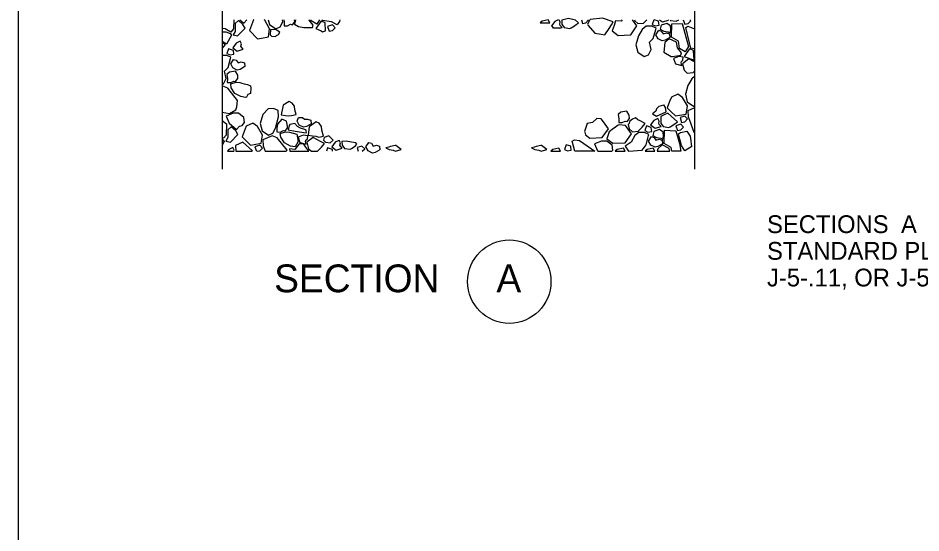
# Model space of a CAD drawing. Extents: x 99862 to 103151, y 100000 to 108153.
# Drawn here: x 99862 to 100674, y 101054 to 101517 of the extents above; entities that cross this region are included whole.
import ezdxf

# ---------------------------------------------------------------- set-up
doc = ezdxf.new("R2010")
doc.units = 0
for name, color, linetype in [('Level 1', 7, 'Continuous'), ('Level 14', 7, 'Continuous'), ('Level 15', 7, 'Continuous'), ('Level 20', 7, 'Continuous'), ('Level 9', 7, 'Continuous')]:
    doc.layers.add(name, color=color, linetype=linetype)

msp = doc.modelspace()

# ---------------------------------------------------------------- linework, layer by layer
at = {"layer": 'Level 1'}
msp.add_lwpolyline([(99862, 99999.5), (103151, 99999.5), (103151, 102075.5), (99862, 102075.5)], close=True, dxfattribs=at)
at = {"layer": 'Level 14'}
for points in [[(100351.01, 101515.54), (100357.28, 101517.09), (100363.3, 101515.48)], [(100349.83, 101508.22), (100343.6, 101508.22), (100342.81, 101509.46)]]:
    msp.add_lwpolyline(points, dxfattribs=at)
at = {"layer": 'Level 15'}
for points in [[(100470.57, 101887.78), (100470.57, 101714.5), (100486.06, 101714.5), (100455.09, 101683.53), (100470.57, 101683.53), (100470.57, 101381.32)], [(100045.57, 101549.08), (100045.57, 101381.32)]]:
    msp.add_lwpolyline(points, dxfattribs=at)
at = {"layer": 'Level 20'}
for p, q in [((100135.92, 101504.91), (100138.62, 101505.77)), ((100106.32, 101397.32), (100123.59, 101397.32)), ((100380.81, 101397.32), (100362.75, 101397.32)), ((100458.16, 101397.32), (100450.04, 101397.32))]:
    msp.add_line(p, q, dxfattribs=at)
for points in [[(100056.06, 101515.66), (100055.65, 101507.47), (100053.3, 101504.62), (100048.44, 101507.37), (100045.57, 101507.74)], [(100061.52, 101515.66), (100065.04, 101512.62), (100067.67, 101515.66)], [(100074.07, 101515.66), (100073.8, 101515.53), (100070.11, 101505.93), (100077.5, 101498.54), (100081.04, 101499.13), (100087.2, 101500.15), (100088.29, 101507.55), (100083.85, 101515.24), (100083.27, 101515.66)], [(100086.99, 101515.66), (100088.09, 101511.29), (100093.86, 101507.45), (100097.77, 101509.15), (100100.14, 101513.88), (100099.74, 101515.66)], [(100101.14, 101515.66), (100101.43, 101513.47), (100101.28, 101510.3), (100104.46, 101510.15), (100107.2, 101511.55), (100108.79, 101511.22), (100110.89, 101513.77), (100110.78, 101515.66)], [(100111.6, 101515.66), (100110.73, 101511.55), (100114.37, 101509.47), (100119.12, 101508.59), (100126.95, 101508.63), (100127.54, 101510.92), (100123.75, 101515.3), (100123.7, 101515.66)], [(100133.14, 101515.66), (100130.63, 101511.7), (100125.75, 101514.8), (100125.61, 101515.66)], [(100138.62, 101505.77), (100138.31, 101513.03), (100134.99, 101514.29), (100134.99, 101514.29), (100134.39, 101514.14), (100129.81, 101507.64), (100134.6, 101505.83), (100135.92, 101504.91)], [(100151.34, 101515.66), (100151.25, 101514.01), (100148.9, 101511.16), (100144.03, 101513.91), (100135.95, 101514.95), (100135.77, 101515.66)], [(100340.31, 101512.84), (100338.8, 101515.58), (100333.4, 101514.48), (100331.59, 101512.84)], [(100331.59, 101512.84), (100340.31, 101512.84)], [(100347.97, 101515.66), (100344.89, 101514.12), (100341.93, 101510.1), (100342.89, 101509.39)], [(100349.48, 101508.22), (100351.38, 101508.8), (100349.71, 101510.5), (100349.31, 101511.6), (100349.73, 101513.54), (100348.68, 101515.66)], [(100351.1, 101515.66), (100351.14, 101511.64), (100353.28, 101508.59), (100358.42, 101507.84), (100359.67, 101508.5), (100362.46, 101510.23), (100362.87, 101510.48), (100366.21, 101512.98), (100363.19, 101515.66)], [(100368.75, 101515.66), (100369.76, 101512.39), (100369.76, 101512.39), (100372.72, 101512.98)], [(100372.72, 101512.98), (100375.23, 101515.49), (100375.07, 101515.66)], [(100376.38, 101515.66), (100374.26, 101511.73), (100374.68, 101510.59), (100380.85, 101503.67), (100386.62, 101502.68), (100389.94, 101502.12), (100393.64, 101507.88), (100395.7, 101511.11), (100397.33, 101513.65), (100387.57, 101516.97), (100376.64, 101515.85)], [(100405.47, 101515.66), (100404.43, 101514.24), (100399.55, 101514.83), (100398.1, 101510.56), (100396.44, 101505.66), (100401.84, 101501.6), (100407.23, 101501.85), (100413.15, 101502.12), (100418.61, 101510.11), (100414.76, 101515.66)], [(100416.45, 101515.66), (100416.67, 101514.76), (100419.44, 101512.29), (100424.61, 101512.73), (100425.68, 101513.66), (100427.68, 101515.66)], [(100433.78, 101515.66), (100432.32, 101511.52), (100432.32, 101511.52), (100435.05, 101510.23)], [(100435.05, 101510.23), (100438.56, 101510.75), (100438.05, 101514.27), (100434.09, 101515.66)], [(100438.86, 101515.66), (100441.55, 101513.68), (100446.98, 101515.34), (100446.67, 101515.66)], [(100448.51, 101515.66), (100448.88, 101515.13), (100454.02, 101514.38), (100455.27, 101515.04), (100456.27, 101515.66)], [(100460.42, 101515.66), (100461.68, 101511.59), (100461.68, 101511.59), (100464.64, 101512.18)], [(100464.64, 101512.18), (100467.15, 101514.69), (100466.19, 101515.66)], [(100045.57, 101504.92), (100048.75, 101504.9), (100052.81, 101503.16), (100054.06, 101501.74), (100049.56, 101493.84), (100045.57, 101496.07)], [(100093.58, 101500.45), (100093.63, 101500.65), (100094.34, 101501.58), (100096.2, 101502.28), (100097.58, 101504.57), (100094.08, 101506.67), (100089.09, 101507), (100088.77, 101502.01), (100089.93, 101501.02)], [(100144.77, 101505.98), (100147.28, 101508.5), (100144.77, 101511.01), (100140.48, 101509.68), (100141.81, 101505.39), (100141.81, 101505.39), (100144.77, 101505.98)], [(100435.87, 101508.15), (100432.1, 101509.77), (100427.03, 101509.81), (100423.49, 101507), (100420.09, 101501.09), (100417.72, 101493.11), (100419.42, 101486.38), (100425.19, 101482.54), (100429.1, 101484.24), (100431.47, 101488.97), (100429.99, 101495.47), (100433.39, 101498.73), (100435.62, 101507.04), (100435.87, 101508.15)], [(100470.57, 101489.62), (100467.28, 101490.04), (100466.05, 101494.88), (100462.55, 101508.69), (100464.53, 101509.88), (100470.57, 101507.55)], [(100089.93, 101501.02), (100093.58, 101500.45)], [(100045.57, 101489.78), (100045.95, 101490.16), (100048.62, 101493.35), (100045.57, 101495)], [(100052.65, 101484.07), (100056.17, 101484.59), (100055.65, 101488.11), (100051.41, 101489.6), (100049.93, 101485.36), (100049.93, 101485.36), (100052.65, 101484.07)], [(100053.47, 101482), (100049.71, 101483.61), (100045.57, 101483.64)], [(100045.57, 101457.59), (100046.7, 101458.08), (100049.07, 101462.81), (100047.59, 101469.31), (100050.99, 101472.57), (100053.22, 101480.88), (100053.47, 101482)], [(100470.57, 101477.67), (100465.35, 101480.49), (100459.76, 101476.11), (100461.2, 101470.23), (100463.97, 101467.76), (100469.14, 101468.2), (100470.21, 101469.13), (100470.57, 101469.48)], [(100470.57, 101464.5), (100468.02, 101462.47), (100464.62, 101456.56), (100462.25, 101448.58), (100463.95, 101441.85), (100469.72, 101438.01), (100470.57, 101438.38)], [(100045.57, 101432.54), (100052.07, 101431.43), (100057.98, 101434.73), (100058.66, 101437.19), (100059.46, 101442.96), (100050.67, 101453.97), (100046.09, 101455.89), (100045.57, 101455.66)], [(100066.53, 101445.83), (100062.39, 101446.51), (100057, 101449.47), (100053.74, 101454.5), (100053.34, 101458.01), (100058.18, 101459.37), (100061.5, 101459.15), (100063.29, 101458.69)], [(100063.29, 101458.69), (100065.27, 101458.1), (100068.38, 101457.41), (100071.13, 101456.16), (100071.49, 101454.03), (100071.04, 101449.41), (100068.81, 101448.48), (100068.07, 101447.3), (100067.51, 101446.15), (100066.53, 101445.83)], [(100108.61, 101440.73), (100106, 101442.2), (100100.62, 101438.88), (100098.77, 101430.23), (100102.53, 101429.43)], [(100102.53, 101429.43), (100105.63, 101429.21), (100107.89, 101429.52), (100112.18, 101430.39), (100111, 101434.53), (100110.81, 101437.78), (100108.61, 101440.73)], [(100086.98, 101435.45), (100082.22, 101430.4), (100079.85, 101422.42), (100081.55, 101415.69), (100087.32, 101411.85), (100091.23, 101413.55), (100093.6, 101418.28), (100096.17, 101428.45), (100096.06, 101434.14), (100091.75, 101435.7), (100086.86, 101435.41)], [(100436.42, 101435.65), (100435.55, 101433.38), (100432.71, 101431.13), (100436.29, 101428.89), (100444.86, 101432.81), (100444.36, 101436.71), (100443.03, 101439.15)], [(100443.03, 101439.15), (100442.59, 101438.83), (100438.27, 101437.66), (100436.42, 101435.65)], [(100470.57, 101436.44), (100464.51, 101433.75), (100464.81, 101428.28), (100465.92, 101425.3), (100468.74, 101417.74), (100469.91, 101414.61), (100470.57, 101414.5)], [(100045.57, 101425.06), (100049.62, 101422.13), (100049.11, 101411.87), (100046.76, 101409.03), (100045.57, 101409.7)], [(100099.13, 101426.22), (100095.35, 101421.79), (100094.89, 101417.87), (100094.75, 101414.7), (100097.92, 101414.55), (100100.66, 101415.95), (100102.25, 101415.62), (100104.35, 101418.17), (100104.24, 101419.93)], [(100104.24, 101419.93), (100103.44, 101424.3), (100099.13, 101426.22)], [(100132.89, 101422.49), (100130.29, 101423.96), (100123.92, 101419.43), (100123.06, 101411.99), (100126.82, 101411.19)], [(100372.3, 101412.07), (100376.2, 101409.14), (100387.51, 101409.65), (100392.97, 101417.64), (100388.62, 101423.92), (100386.62, 101426.44), (100382.55, 101426.87), (100378.79, 101423.23), (100373.91, 101422.36), (100371.49, 101415.23)], [(100419.59, 101425.77), (100417.38, 101427.57), (100414.78, 101426.33), (100411.98, 101424.21), (100411.6, 101422.4), (100410.86, 101421.4)], [(100410.86, 101421.4), (100411.83, 101417.46), (100414.6, 101414.99), (100419.77, 101415.43), (100420.84, 101416.36), (100423.5, 101419.02), (100426.18, 101422.21), (100421.68, 101424.64), (100419.59, 101425.77)], [(100461.78, 101423.92), (100464.29, 101426.43), (100461.78, 101428.95), (100457.49, 101427.62), (100458.82, 101423.33), (100458.82, 101423.33), (100461.78, 101423.92)], [(100105.81, 101420.42), (100105.02, 101416.74), (100111.4, 101415.37), (100121.25, 101413.82), (100121.55, 101414.99)], [(100121.55, 101414.99), (100120.73, 101416.53), (100116.07, 101418.1), (100113.22, 101419.53), (100110.88, 101422.26), (100106.45, 101421.55), (100105.81, 101420.42)], [(100126.82, 101411.19), (100129.91, 101410.97), (100132.42, 101410.07), (100136.71, 101410.93), (100135.28, 101416.29), (100135.09, 101419.54), (100132.89, 101422.49)], [(100371.49, 101415.23), (100371.77, 101414.48), (100372.3, 101412.07)], [(100393.68, 101414.93), (100391.54, 101408.61), (100396.94, 101404.55), (100408.25, 101405.07), (100413.71, 101413.06), (100409.35, 101419.33), (100408.38, 101420.56)], [(100408.38, 101420.56), (100402.72, 101421.22), (100401.71, 101420.83), (100398.3, 101418.11), (100397.55, 101417.85), (100393.69, 101414.93), (100393.68, 101414.93)], [(100428.51, 101414.63), (100432.03, 101415.15), (100431.51, 101418.67), (100427.27, 101420.15), (100425.78, 101415.92), (100425.78, 101415.92), (100428.51, 101414.63)], [(100450.04, 101397.32), (100449.5, 101400.65), (100443.15, 101404.35), (100443.55, 101416.26), (100453.65, 101415.84), (100456.94, 101404.25), (100458.16, 101397.32)], [(100458.1, 101416.58), (100460.61, 101419.09), (100458.1, 101421.61), (100453.81, 101420.28), (100455.14, 101415.99), (100455.14, 101415.99), (100458.1, 101416.58)], [(100467.94, 101401.78), (100461.86, 101397.7), (100458.66, 101402.61), (100457.22, 101408.29), (100456.01, 101413.09), (100457.99, 101414.28), (100463.66, 101415.3), (100466.59, 101410.96), (100467.17, 101406.81), (100467.61, 101403.71), (100467.88, 101401.71)], [(100045.57, 101407.86), (100046.27, 101407.56), (100047.52, 101406.14), (100045.57, 101402.73)], [(100103.28, 101397.32), (100103.99, 101398.43), (100095.2, 101409.44), (100090.62, 101411.36), (100082.12, 101407.59), (100082.41, 101402.12), (100084.2, 101397.32)], [(100128.98, 101397.32), (100131.27, 101397.51), (100132.35, 101398.44), (100135.01, 101401.1), (100137.68, 101404.29), (100134.11, 101406.22), (100127.49, 101409.8), (100121.89, 101405.42), (100123.33, 101399.55), (100125.82, 101397.32)], [(100142.89, 101404.81), (100145.41, 101407.32), (100141.55, 101411.18), (100137.26, 101409.85), (100136.84, 101407.44), (100138.59, 101405.56), (100142.96, 101404.82)], [(100150.02, 101406.87), (100147.15, 101405.44), (100144.19, 101401.42), (100148.21, 101398.46), (100153.64, 101400.12), (100151.98, 101401.82), (100151.57, 101402.92), (100151.99, 101404.86), (100151.1, 101406.65)], [(100151.1, 101406.65), (100150.59, 101406.75), (100150.02, 101406.87)], [(100362.75, 101397.32), (100360.41, 101406.55), (100362.39, 101407.74), (100367.03, 101406.97), (100370.99, 101404.42), (100380.81, 101397.32)], [(100429.33, 101412.55), (100425.56, 101414.17), (100420.49, 101414.21), (100416.95, 101411.4), (100413.55, 101405.49), (100408.1, 101401.8), (100411.23, 101397.32)], [(100411.12, 101397.33), (100423.45, 101398.41), (100426.85, 101403.13), (100429.08, 101411.44), (100429.33, 101412.55)], [(100056.18, 101397.32), (100056.39, 101398.32), (100055.2, 101400.72), (100051.55, 101398.9), (100050.38, 101397.32)], [(100072.27, 101397.32), (100072.87, 101397.77), (100064.19, 101405.45), (100057.74, 101402.47), (100057.8, 101397.32)], [(100079.38, 101397.76), (100081.89, 101400.28), (100079.38, 101402.79), (100075.1, 101401.46), (100076.38, 101397.32)], [(100123.59, 101397.32), (100120.92, 101401.16), (100118.92, 101403.69), (100114.86, 101404.12), (100111.09, 101399.02), (100106.21, 101399.61), (100106.32, 101397.32)], [(100144.96, 101397.32), (100144.71, 101399.05), (100140.47, 101400.54), (100139.34, 101397.32)], [(100166.65, 101403.71), (100165.93, 101404.97), (100161.79, 101405.68), (100157.28, 101406.41), (100153.37, 101406.22)], [(100153.37, 101406.22), (100153.41, 101402.96), (100155.54, 101399.91), (100160.68, 101399.17), (100161.93, 101399.82), (100165.13, 101401.8), (100166.65, 101403.71)], [(100171.66, 101397.32), (100173.82, 101399.48), (100171.3, 101401.99), (100167.02, 101400.66), (100168.05, 101397.32)], [(100192.81, 101400.53), (100195.7, 101398.92), (100199.47, 101398.41), (100201.42, 101397.56), (100206.66, 101398.88), (100201.76, 101402.63)], [(100201.76, 101402.63), (100201.09, 101402.46), (100197.11, 101401.51), (100195.49, 101401.12), (100192.81, 101400.53)], [(100323.9, 101400.53), (100326.79, 101398.92), (100330.56, 101398.41), (100332.52, 101397.56), (100337.75, 101398.88), (100332.85, 101402.63)], [(100332.85, 101402.63), (100332.18, 101402.46), (100328.2, 101401.51), (100326.58, 101401.12), (100323.9, 101400.53)], [(100350, 101397.32), (100348.48, 101400.06), (100343.08, 101398.95), (100341.28, 101397.32)], [(100356.12, 101397.77), (100359.64, 101398.29), (100359.12, 101401.8), (100354.89, 101403.29), (100353.4, 101399.05), (100353.4, 101399.05), (100356.12, 101397.77)], [(100396.19, 101397.32), (100396.93, 101398.31), (100396.33, 101402.75), (100391.6, 101406.59), (100386.87, 101406.59), (100380.67, 101403.93), (100383.33, 101397.72), (100383.8, 101397.32)], [(100407.98, 101397.32), (100406.46, 101400.06), (100401.06, 101398.95), (100399.25, 101397.32)], [(100434.91, 101397.32), (100433.39, 101400.06), (100428, 101398.95), (100426.19, 101397.32)], [(100448.14, 101397.32), (100447.97, 101398.34), (100447.71, 101399.98), (100441.28, 101403.01), (100437.36, 101399.69), (100436.86, 101397.32)], [(100050.38, 101397.32), (100056.18, 101397.32)], [(100057.8, 101397.32), (100072.27, 101397.32)], [(100077.15, 101397.32), (100079.38, 101397.76)], [(100084.2, 101397.32), (100103.28, 101397.32)], [(100125.82, 101397.32), (100128.98, 101397.32)], [(100341.28, 101397.32), (100350, 101397.32)], [(100383.8, 101397.32), (100396.19, 101397.32)], [(100399.25, 101397.32), (100407.98, 101397.32)], [(100426.19, 101397.32), (100434.91, 101397.32)], [(100436.86, 101397.32), (100445.73, 101397.32), (100448.14, 101397.32)]]:
    msp.add_lwpolyline(points, dxfattribs=at)
for points in [[(100066.15, 101507.96), (100064.31, 101511.43), (100060.26, 101514.89), (100057.28, 101512.25), (100057.24, 101505.19), (100055.38, 101502.09), (100059.52, 101501.26)], [(100446.66, 101504.75), (100448.61, 101503.9), (100449.09, 101506.6), (100448.87, 101510.14), (100445.62, 101512.43), (100440.52, 101510.73), (100439.56, 101507.11), (100442.89, 101505.27)], [(100445.21, 101503.82), (100448.06, 101502.97), (100448.28, 101499.65), (100444.11, 101497.17), (100441.52, 101496.58), (100437.68, 101498.58), (100435.68, 101502.12), (100438.3, 101506.15), (100440.59, 101505.41), (100442.33, 101502.94)], [(100450.09, 101511.86), (100459.26, 101512.15), (100465.06, 101491.67), (100461.95, 101486.79), (100457.08, 101489.89), (100456.04, 101496.25), (100449.69, 101499.94)], [(100062.51, 101491.98), (100062.93, 101493.92), (100061.74, 101496.32), (100058.09, 101494.5), (100055.13, 101490.48), (100059.15, 101487.52), (100064.58, 101489.18), (100062.92, 101490.88)], [(100454.25, 101495.58), (100447.82, 101498.61), (100443.9, 101495.29), (100442.77, 101486.64), (100449.53, 101482.69), (100450.77, 101482.49), (100458.28, 101483.72), (100458.87, 101486.01), (100455.08, 101490.39)], [(100465.72, 101489.23), (100461.14, 101482.72), (100470.16, 101479.32), (100469.64, 101488.12), (100466.31, 101489.38), (100466.31, 101489.38)], [(100062.82, 101477.67), (100065.66, 101476.82), (100065.88, 101473.49), (100061.71, 101471.01), (100059.12, 101470.42), (100055.28, 101472.42), (100053.28, 101475.97), (100055.91, 101479.99), (100058.2, 101479.26), (100059.93, 101476.78)], [(100458.72, 101477.96), (100460.12, 101479.36), (100460.42, 101482.02), (100456.36, 101482.47), (100451.7, 101480.69), (100453.48, 101476.03), (100458.94, 101474.48), (100458.46, 101476.81)], [(100056.13, 101460.48), (100057.72, 101460.15), (100059.82, 101462.7), (100059.64, 101465.69), (100057.53, 101469.5), (100052.14, 101468.39), (100049.85, 101466.32), (100050.36, 101462.4), (100050.22, 101459.23), (100053.39, 101459.08)], [(100464.14, 101438.11), (100459.71, 101445.8), (100455.57, 101448.75), (100449.66, 101446.09), (100448.09, 101442.02), (100445.96, 101436.49), (100449.55, 101432.9), (100453.35, 101429.09), (100456.9, 101429.69), (100463.06, 101430.71)], [(100065.6, 101423.23), (100065.01, 101427.66), (100060.28, 101431.5), (100055.55, 101431.5), (100049.34, 101428.84), (100052, 101422.63), (100058.5, 101417.02), (100061.15, 101420.08), (100063.53, 101420.42)], [(100408.22, 101424.51), (100409.81, 101424.18), (100411.91, 101426.73), (100411.73, 101429.72), (100409.62, 101433.53), (100404.23, 101432.42), (100401.94, 101430.35), (100402.45, 101426.43), (100402.31, 101423.25), (100405.48, 101423.1)], [(100448.73, 101419.44), (100451.93, 101421.42), (100455.27, 101423.93), (100449.46, 101429.07), (100446.59, 101431.61), (100443.89, 101430.36), (100440.14, 101428.62), (100440.2, 101422.58), (100442.34, 101419.53), (100447.48, 101418.78)], [(100122.49, 101426.21), (100125.34, 101425.36), (100125.56, 101422.03), (100121.38, 101419.55), (100118.79, 101418.96), (100114.95, 101420.96), (100112.96, 101424.51), (100114.3, 101427.64), (100117.87, 101427.8), (100119.61, 101426.27)], [(100438.37, 101422.54), (100438.79, 101424.48), (100437.6, 101426.88), (100433.95, 101425.06), (100430.99, 101421.04), (100435.01, 101418.08), (100440.44, 101419.74), (100438.77, 101421.44)], [(100059.61, 101412.36), (100057.77, 101415.83), (100053.72, 101419.29), (100050.74, 101416.65), (100050.7, 101409.6), (100048.84, 101406.49), (100052.98, 101405.66)], [(100081.75, 101411.95), (100077.31, 101419.64), (100073.17, 101422.6), (100067.26, 101419.93), (100063.57, 101410.33), (100070.96, 101402.94), (100074.5, 101403.53), (100080.66, 101404.55)], [(100440.12, 101409.15), (100442.07, 101408.3), (100442.55, 101411), (100442.33, 101414.54), (100439.08, 101416.84), (100433.98, 101415.14), (100433.02, 101411.51), (100436.35, 101409.67)], [(100106.03, 101414.62), (100112.83, 101412.85), (100113.35, 101409.45), (100113.87, 101406.05), (100111.36, 101401.25), (100106.92, 101401.98), (100101.53, 101404.94), (100098.27, 101409.97), (100097.87, 101413.48), (100102.71, 101414.84)], [(100120.85, 101407.27), (100122.26, 101408.67), (100122.55, 101411.33), (100118.5, 101411.78), (100113.83, 101410), (100115.61, 101405.34), (100121.07, 101403.8), (100120.59, 101406.12)], [(100438.67, 101408.23), (100441.52, 101407.38), (100441.74, 101404.05), (100437.57, 101401.57), (100434.98, 101400.98), (100431.14, 101402.98), (100429.14, 101406.53), (100431.76, 101410.55), (100434.06, 101409.81), (100435.79, 101407.34)], [(100184.41, 101402.94), (100187.26, 101402.09), (100187.48, 101398.77), (100183.3, 101396.29), (100180.72, 101395.7), (100176.87, 101397.7), (100174.88, 101401.24), (100177.5, 101405.27), (100179.79, 101404.53), (100181.53, 101402.06)]]:
    msp.add_lwpolyline(points, close=True, dxfattribs=at)
at = {"layer": 'Level 9'}
msp.add_circle((100303.86, 101280.07), 37.5, dxfattribs=at)

# ---------------------------------------------------------------- texts
at = {"layer": 'Level 20'}
for s, height, p in [('SECTIONS ', 16, (100535.71, 101323.76)), ('A', 16, (100656.21, 101323.76)), ('STANDARD PLAN J-50.10, ', 16, (100535.71, 101299.76)), ('SECTION', 25, (100092.38, 101270.54)), ('A', 25, (100292.31, 101270.54)), ('J-5-.11, OR J-50.12', 16, (100535.71, 101275.76))]:
    msp.add_text(s, height=height, dxfattribs=at).set_placement(p)

doc.saveas('drawing.dxf')
